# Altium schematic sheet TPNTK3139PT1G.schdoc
size 127 x 101 mm
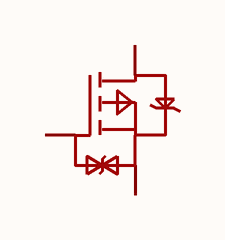
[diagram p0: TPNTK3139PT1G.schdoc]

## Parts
Q?  tpntk3139pt1g  [SOT-723_L1.2-W0.8-P0.40-LS1.2-BR]  (value not drawn)

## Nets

Not connected (* = marked no-connect by the designer): Q? 1(G) 2(S) 3(D)

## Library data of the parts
Q? = tpntk3139pt1g: 类型:1个P沟道;漏源电压(Vdss):20V;连续漏极电流(Id):850mA;导通电阻(RDS(on)):730mΩ@2.5V,0.45A;耗散功率(Pd):690mW;阈值电压(Vgs(th)):500mV;; Manufacturer: TECH PUBLIC(台舟); AddInBom: yes; ModelId: abccde1e67074d7481274a37cf5c97f0; ModelName: SOT-723-3P_L1.2-W0.8-H0.6-LS1.2-P0.40; ModelTransform: 47.244,47.244,0,180,0,0,0,0,0; Type: 1个P沟道; Drain to Source Voltage: 20V; Current - Continuous Drain(Id): 850mA; Pd - Power Dissipation: 690mW; Gate Threshold Voltage (Vgs(th)@Id): 500mV; Gate Charge(Qg): 530pC; Input Capacitance(Ciss@Vds): 58pF@10V; Reverse Transfer Capacitance (Crss@Vds): 4.4pF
